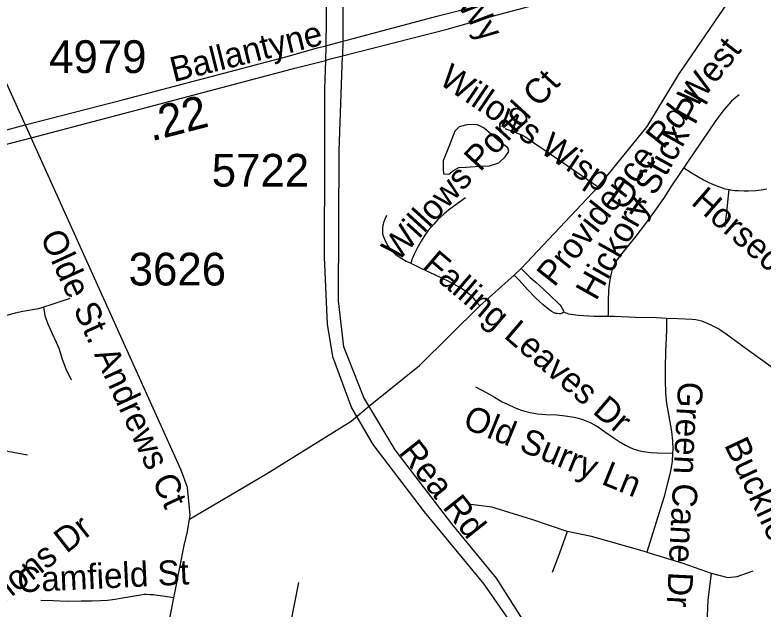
# Model space of a CAD drawing. Extents: x 1383679 to 1536984, y 460658 to 651027.
# Drawn here: x 1456433 to 1459289, y 478901 to 481168 of the extents above; entities that cross this region are included whole.
import ezdxf

# ---------------------------------------------------------------- set-up
doc = ezdxf.new("R2010")
doc.units = 0
for name, color, linetype in [('Exist Hydrographic Misc Water Feature', 7, 'Continuous'), ('Exist Road Non-System Type 51', 7, 'Continuous'), ('Exist Road Non-System Type 51 Label', 7, 'Continuous'), ('Exist Road Secondary Mileage Hundredths English Label', 7, 'Continuous'), ('Exist Road Secondary Type 51 Attributed', 7, 'Continuous'), ('Exist Road Secondary Type 51 Divided Attributed', 7, 'Continuous'), ('Exist Road Secondary Type 51 Label', 7, 'Continuous'), ('Exist Road Secondary Type 51 Number Label', 7, 'Continuous')]:
    doc.layers.add(name, color=color, linetype=linetype)

msp = doc.modelspace()

# ---------------------------------------------------------------- linework, layer by layer
at = {"layer": 'Exist Hydrographic Misc Water Feature'}
msp.add_lwpolyline([(1458093.6, 480674.9), (1458068.4, 480611.4), (1458067.8, 480579.4), (1458069.6, 480561.3), (1458089.6, 480560.9), (1458107.7, 480574.5), (1458128, 480586.4), (1458154.1, 480587.5), (1458208.1, 480590.5), (1458244.2, 480592.3), (1458280.4, 480603.8), (1458304.9, 480627.2), (1458319.2, 480646.5), (1458315.4, 480660.6), (1458283.9, 480683.4), (1458254.3, 480710.2), (1458224.8, 480736.3), (1458199, 480749.1), (1458163, 480749.8), (1458128.9, 480740.7), (1458112.5, 480724.6), (1458093.6, 480674.9)], dxfattribs=at)
at = {"layer": 'Exist Road Non-System Type 51'}
for points in [[(1457099.8, 479243.5), (1457393.8, 479416.6), (1457716, 479617.4), (1457789, 479678.2), (1457977.4, 479830.3), (1458207.6, 480058.4), (1458339.2, 480175), (1458365.3, 480200.6), (1458660, 480511.9), (1458846.8, 480742.9), (1458968.4, 480943.7), (1459153.1, 481213.1), (1459169, 481314.8), (1459179.9, 481370.3)], [(1459197.6, 480863.1), (1459186.3, 480854.4), (1459169, 480839), (1459140.7, 480807.4), (1459123.9, 480786), (1459109.2, 480765), (1459077.4, 480718.2), (1459030.4, 480649.2), (1458940, 480515.5), (1458908.7, 480468), (1458875.2, 480419.8), (1458840, 480371.8), (1458803.1, 480323.6), (1458766.4, 480277.7), (1458743.9, 480250.4), (1458730.2, 480230.5), (1458725.2, 480222.6), (1458717.2, 480206.5), (1458713.4, 480196.7), (1458710.1, 480186), (1458706.4, 480169.6), (1458703.4, 480149), (1458699.6, 480117.5), (1458697.5, 480075.2), (1458697.3, 480028.2), (1458697, 480016.9)], [(1453499, 480715.7), (1453710.5, 480715.7), (1453906, 480704.1), (1454087.5, 480678.9), (1454259, 480646), (1454560.2, 480564.8), (1454789.6, 480500.9), (1454947.2, 480479.6), (1455132.7, 480473.8), (1455334.2, 480483.5), (1455503.7, 480508.6), (1455787, 480580.2), (1456024.3, 480627.2), (1456214.6, 480678.6), (1456472, 480748.3)], [(1458303.7, 480734.9), (1458351.6, 480716.8), (1458367.3, 480710.1), (1458379.7, 480703.7), (1458395.5, 480694.3), (1458413.4, 480681.7), (1458479.9, 480636), (1458660, 480511.9)], [(1453202.5, 480619.8), (1453365.5, 480646.1), (1453471.5, 480656.7), (1453585.6, 480664.6), (1453794.8, 480659.3), (1454006.8, 480632.9), (1454148.1, 480603.9), (1454398.1, 480553.8), (1454626.3, 480493.2), (1454737.7, 480456.3), (1454887.2, 480435.2), (1454995.9, 480422), (1455120.9, 480416.8), (1455196.9, 480414.1), (1455330.1, 480424.7), (1455501.3, 480456.3), (1455672.5, 480495.9), (1455972.2, 480562.9), (1456222.2, 480628.6), (1456494.2, 480699.2)], [(1458987.1, 480584.4), (1459018.4, 480564.3), (1459061.6, 480539.1), (1459079.4, 480530.2), (1459096.5, 480522.4), (1459119.4, 480513.2), (1459130.7, 480509), (1459140, 480506.2), (1459160, 480502.1)], [(1459144.2, 480360.3), (1459151.7, 480428.1), (1459157.6, 480478.3), (1459160, 480502.1)], [(1459160, 480502.1), (1459163.7, 480501.3), (1459181.3, 480498.6), (1459195.3, 480497.8), (1459217.8, 480496.5), (1459234.4, 480496.9), (1459262.2, 480498.7), (1459281.6, 480500.8), (1459304.1, 480504.3)], [(1458152.8, 480470.7), (1458106.9, 480437.3), (1458088.1, 480423.4), (1458070.7, 480408.2), (1458047.9, 480387.2), (1458031.8, 480369.8), (1458010.8, 480345.3), (1457998.1, 480328.1), (1457984.2, 480305.4), (1457968.8, 480278.6), (1457958.1, 480257.2), (1457950, 480237.3), (1457944, 480220.7)], [(1457851.8, 480402.7), (1457846.3, 480391.7), (1457841.8, 480379.2), (1457838, 480366.1), (1457836.2, 480353.8), (1457835.7, 480346.3), (1457835.9, 480336.7), (1457837.8, 480328.2), (1457840.9, 480318.8), (1457846.2, 480306.2), (1457856.4, 480287.5), (1457864.2, 480275.9), (1457872.5, 480266.2), (1457884.6, 480255.7), (1457909.8, 480238.4), (1457927.2, 480228.8), (1457944, 480220.7)], [(1457944, 480220.7), (1457984.8, 480201), (1458034.7, 480177.1), (1458087.7, 480151.5), (1458121.9, 480134.1), (1458138.2, 480125), (1458150.8, 480116.1), (1458168, 480101.9), (1458178.7, 480091.7), (1458185.5, 480084.5), (1458195.7, 480071.8), (1458207.6, 480058.4)], [(1458365.3, 480200.6), (1458376.8, 480188.7), (1458400.1, 480166.2), (1458423.4, 480146.7), (1458451.5, 480121.4), (1458478.7, 480095.4), (1458505.9, 480069.7), (1458513.1, 480062), (1458518.3, 480055.8), (1458524.1, 480045.4), (1458527, 480038.9), (1458528.8, 480033.7)], [(1458528.8, 480033.7), (1458521.7, 480029.7), (1458515.3, 480027.5), (1458511.9, 480027.3), (1458502.7, 480028.1), (1458498, 480029.3), (1458489, 480032.5), (1458480.3, 480037.9), (1458471.7, 480043.8), (1458449.8, 480061.3), (1458420.5, 480088.3), (1458390.5, 480120.9), (1458357.6, 480156.4), (1458339.2, 480175)], [(1456642.5, 480085.6), (1456565.5, 480061), (1456541.2, 480053.1)], [(1456541.2, 480053.1), (1456522.8, 480047), (1456462.8, 480036.3), (1456433.1, 480029.8), (1456371.1, 480013.1)], [(1456541.2, 480053.1), (1456546.2, 480021.4), (1456557, 479991.4), (1456573.8, 479954.3), (1456590.5, 479919.6), (1456600.1, 479896.8), (1456613.4, 479854.9), (1456627.6, 479817.8), (1456646.9, 479775.8)], [(1458697, 480016.9), (1458645, 480017.4), (1458582.9, 480021.6), (1458547.9, 480026.5), (1458528.8, 480033.7)], [(1458920.9, 480010.2), (1458883.1, 480012), (1458801.7, 480014), (1458722.2, 480016.7), (1458697, 480016.9)], [(1458920.9, 480010.2), (1458920.1, 479966.2), (1458917.1, 479880.5), (1458915.1, 479825.5), (1458915.1, 479771.7), (1458917.3, 479725.8), (1458921, 479685.3), (1458925.5, 479656.9), (1458931.8, 479621.6), (1458939.7, 479578.1), (1458943.7, 479542.6), (1458944.6, 479509.8), (1458943.9, 479495.9)], [(1459382, 479778), (1459325.4, 479821.1), (1459225, 479894.4), (1459149.1, 479949.9), (1459128.6, 479963.5), (1459116.5, 479971.1), (1459103.9, 479978.2), (1459088.3, 479986), (1459070.5, 479993.7), (1459055, 479999.1), (1459044, 480002), (1459032.9, 480004.5), (1459018.2, 480006.3), (1458963.4, 480008.3), (1458920.9, 480010.2)], [(1458191.6, 479749.2), (1458237.5, 479724.4), (1458263.3, 479708.9), (1458293.5, 479692), (1458315.9, 479680.8), (1458340.4, 479669.9), (1458361.4, 479661.6), (1458379.1, 479656.4), (1458399.7, 479650.9), (1458428.7, 479645.5), (1458444.3, 479643.9), (1458460, 479643.5), (1458501.8, 479641.5), (1458533.1, 479638.7), (1458567.8, 479632.9), (1458583.8, 479629.2), (1458600.1, 479624.6), (1458610.6, 479620.7), (1458628.6, 479612.8), (1458648.6, 479602.2), (1458660.4, 479595.1), (1458684.4, 479578), (1458721.1, 479552.8), (1458740.4, 479539.8), (1458763.9, 479526.4), (1458778.8, 479518.2), (1458793.6, 479512.5), (1458813.2, 479506), (1458831.2, 479501.9), (1458842.2, 479500.3), (1458861.1, 479498.6), (1458884.6, 479497.3), (1458943.9, 479495.9)], [(1456480.5, 479488.2), (1456294.6, 479522.8), (1456290.9, 479454.7), (1456288.8, 479398.5), (1456286.5, 479371.5), (1456285.8, 479361.4)], [(1458943.9, 479495.9), (1458942.4, 479465.6), (1458938, 479440.6), (1458932.9, 479415.8), (1458925, 479381.3), (1458910.5, 479326.8), (1458845, 479117.2)], [(1458541.1, 479197.2), (1458406.7, 479242), (1458253.2, 479290.1), (1458173.2, 479299.7)], [(1458541.1, 479197.2), (1458512.3, 479114), (1458483.5, 479040.3)], [(1458845, 479117.2), (1458633.8, 479178), (1458541.1, 479197.2)], [(1458845, 479117.2), (1458982.5, 479075.6), (1459091.3, 479037.1)], [(1459091.3, 479037.1), (1459155.2, 479021.1), (1459190.4, 479024.3), (1459251.2, 479046.7)], [(1459091.3, 479037.1), (1459078.5, 478934.7), (1459075.3, 478845), (1459030.5, 478736.2)], [(1457515.9, 479001.6), (1457485.1, 478846.8), (1457480.6, 478811.8), (1457483, 478802.8), (1457489.1, 478797.4), (1457564.8, 478782.6)], [(1457039.6, 478943.2), (1456997.9, 478949.4), (1456976.8, 478952.3), (1456962.1, 478954.5), (1456948.7, 478955.4), (1456934, 478955.9), (1456924.3, 478955.5), (1456913.3, 478954.2), (1456888.6, 478950.1), (1456866, 478946.3), (1456843.2, 478942), (1456815.8, 478937.6), (1456785.7, 478933.8), (1456760, 478932), (1456725.7, 478931.1), (1456685.5, 478930.2), (1456633.7, 478930), (1456578.8, 478931.9), (1456530.9, 478932.8)]]:
    msp.add_lwpolyline(points, dxfattribs=at)
at = {"layer": 'Exist Road Secondary Type 51 Attributed'}
for points in [[(1455135.8, 483072), (1455511.9, 482538.5), (1455640.3, 482366.3), (1455766.5, 482173.6), (1455847, 482046.7), (1455900.8, 481978.7), (1455952.1, 481875.7), (1455974.3, 481838.4), (1455998.2, 481794.3), (1456021.5, 481746.2), (1456046.2, 481696), (1456071.2, 481642.8), (1456075, 481634.1), (1456227.8, 481288.6), (1456472, 480748.3)], [(1456472, 480748.3), (1456494.2, 480699.2)], [(1456427.3, 477070.2), (1456464.2, 477077), (1456534.3, 477098.6), (1456542.8, 477104.2), (1456585.7, 477158.9), (1456611.4, 477202.6), (1456636.6, 477266.2), (1456653.7, 477321), (1456829.7, 477934.5), (1456869, 478083.4), (1456883.3, 478148.5), (1456909.6, 478279.4), (1456951.5, 478498.5), (1457079.3, 479143.2), (1457091.1, 479196.8), (1457099.8, 479243.5), (1457101.4, 479259), (1457091.2, 479364.1), (1457067.4, 479430.8), (1456494.2, 480699.2)]]:
    msp.add_lwpolyline(points, dxfattribs=at)
at = {"layer": 'Exist Road Secondary Type 51 Divided Attributed'}
for points in [[(1457449.7, 481850.6), (1457520.1, 481715.4), (1457560.4, 481629.9), (1457588.6, 481558.5), (1457615.8, 481458), (1457622.4, 481406.3), (1457622.4, 481316.2), (1457622.4, 481249.5), (1457620.1, 481050.7)], [(1457521.2, 481866.1), (1457583, 481740.7), (1457616.8, 481660.9), (1457642, 481581.6), (1457669.3, 481488.1), (1457683.4, 481396), (1457684.8, 481289.3), (1457684.6, 481067.7)], [(1457683.3, 481012.4), (1457743.3, 481027.4), (1458088, 481115.4), (1458256.6, 481163.8), (1458585.7, 481253.1), (1458779.3, 481311.5), (1459020.9, 481392.4), (1459455.3, 481552.2), (1459733.6, 481652.9), (1459817.2, 481689.6)], [(1457684.6, 481067.7), (1457705.5, 481073.2), (1458044.1, 481163.8), (1458222.2, 481207.7), (1458554.6, 481298.3), (1458782.1, 481367), (1459206.1, 481506.2), (1459443.1, 481587.1), (1459539.9, 481619), (1459643.3, 481645.4), (1459817.2, 481689.6)], [(1456472, 480748.3), (1456848, 480845.4), (1457466.9, 481008), (1457588.2, 481042.4), (1457620.1, 481050.7)], [(1457620.1, 481050.7), (1457618.7, 480994.9)], [(1457620.1, 481050.7), (1457684.6, 481067.7)], [(1457684.6, 481067.7), (1457683.3, 481012.4)], [(1456494.2, 480699.2), (1456870.8, 480798.5), (1457506.5, 480966.5), (1457618.7, 480994.9)], [(1457618.7, 480994.9), (1457614.2, 480886.1), (1457614.2, 480629.6), (1457614, 480244), (1457625.4, 479987.5), (1457645.3, 479865), (1457717.2, 479668.5), (1457799.1, 479528.7), (1457995.2, 479271.7), (1458223, 478995.3), (1458353.9, 478807.2), (1458442.2, 478630.5), (1458527.6, 478391.1), (1458613.1, 477994.2), (1458834.8, 476764.4), (1458916.6, 476255.7), (1458923.1, 476147), (1458926, 476018.8), (1458798.2, 475346.4), (1458786.6, 475132.1)], [(1457618.7, 480994.9), (1457632.7, 480999.5), (1457683.3, 481012.4)], [(1458837.8, 475143.5), (1458860.6, 475380), (1458940.2, 475785.1), (1458975, 476071.6), (1458974.4, 476215.4), (1458954.5, 476349.3), (1458884.4, 476793.7), (1458630.1, 478157.4), (1458544.7, 478502.2), (1458470.7, 478670.4), (1458422.3, 478781.5), (1458271.4, 479018.1), (1458100.5, 479226.1), (1457884.5, 479508.8), (1457764.8, 479708.1), (1457688, 479902.1), (1457668.3, 480076.8), (1457671.2, 480649.6), (1457683.3, 481012.4)]]:
    msp.add_lwpolyline(points, dxfattribs=at)

# ---------------------------------------------------------------- texts
at = {"layer": 'Exist Road Non-System Type 51 Label'}
for s, rotation, p in [('Gallant Fox Wy', 305.4213, (1457720.8, 481765.4)), ('Providence Rd West', 51.64, (1458491.9, 480126.4)), ('Willows Wisp Dr', 325.8549, (1458046.9, 480908.4)), ('Willows Pond Ct', 47.5605, (1457894.8, 480223)), ('Hickory Stick Pl', 60.6903, (1458651.6, 480074.1)), ('Horsecroft Ct', 318.9759, (1459010.7, 480448.2)), ('Falling Leaves Dr', 319.5728, (1457984, 480204.8)), ('Green Cane Dr', 267.0593, (1458965.5, 479770.2)), ('Old Surry Ln', 337.8687, (1458138.3, 479594.4)), ('Buckfield Pl', 295.2508, (1459139.7, 479527.3)), ('Southgate Commons Dr', 38.1699, (1455663.6, 478351.2)), ('Camfield St', 2.7499, (1456443.4, 478963.6))]:
    msp.add_text(s, height=95, rotation=rotation, dxfattribs=at).set_placement(p)
at = {"layer": 'Exist Road Secondary Mileage Hundredths English Label'}
msp.add_text('.22', height=125, rotation=14.5258, dxfattribs=at).set_placement((1456953.9, 480685.5))
at = {"layer": 'Exist Road Secondary Type 51 Label'}
for s, rotation, p in [('Ballantyne', 14.0849, (1457038.9, 480911.4)), ('Olde St. Andrews Ct', 294.6791, (1456527.2, 480322.5)), ('Rea Rd', 308.5158, (1457895.5, 479498.3))]:
    msp.add_text(s, height=95, rotation=rotation, dxfattribs=at).set_placement(p)
at = {"layer": 'Exist Road Secondary Type 51 Number Label'}
for s, p in [('4979', (1456563.2, 480946.6)), ('5722', (1457184.2, 480512.9)), ('3626', (1456866.9, 480135.6))]:
    msp.add_text(s, height=125, dxfattribs=at).set_placement(p)

doc.saveas('drawing.dxf')
